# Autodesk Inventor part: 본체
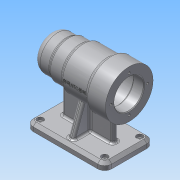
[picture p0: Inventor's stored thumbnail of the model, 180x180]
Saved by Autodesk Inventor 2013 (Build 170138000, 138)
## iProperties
Created: 2016-06
Part Number: 본체
Material: 알루미늄 6061
Document SubType Name: Modeling
Designer: Administrator
Density: 2.71 g/cm^3
Mass: 693.6 g
Surface Area: 666.256 cm^2
Volume: 255.941 cm^3
Author: Administrator
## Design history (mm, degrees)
sketch "스케치1"
  geometry: L1 (-46, 35)-(46, 35); L2 (56, 25)-(56, -25); L3 (46, -35)-(-46, -35); L4 (-56, -25)-(-56, 25); A1 r 10 centre (-46, 25) between (-46, 35) and (-56, 25); A2 r 10 centre (-46, -25) between (-56, -25) and (-46, -35); A3 r 10 centre (46, -25) between (46, -35) and (56, -25); A4 r 10 centre (46, 25) between (56, 25) and (46, 35); 3 further points
  constraints: 8 end point, 8 point on circle, 8 tangent, 4 centre point, 3 equal radius, 2 midpoint, 2 parallel, 1 horizontal, 1 horizontal alignment, 1 perpendicular, 1 vertical alignment
  dimensions: "d0" = 112 distance between parallel lines of L2 L4; "d2" = 70 distance between parallel lines of L1 L3; "d3" = 10 radius of A1
extrude "돌출1" new body sketch "스케치1" distance "d4" = 10; taper "d5" = 0 deg
sketch "스케치2"
  geometry: L1 (-56, 0)-(-56, 10) reference; L2 (-46, 10)-(-56, 10) reference; L3 (46, 10)-(-46, 10) reference; L4 (56, 10)-(46, 10) reference; L5 (56, 0)-(56, 10) reference; L6 (56, 0)-(46, 0) reference; L7 (46, 0)-(-46, 0) reference; L8 (-46, 0)-(-56, 0) reference; L9 (-56, 80)-(56, 80); L10 (56, 80)-(56, 114); L11 (56, 114)-(28, 114); L12 (28, 114)-(28, 110); L13 (28, 110)-(-11, 110); L14 (-11, 110)-(-11, 107); L15 (-11, 107)-(-31, 107); L16 (-31, 107)-(-31, 105); L17 (-31, 105)-(-46, 105); L18 (-56, 95)-(-56, 80); A1 r 10 centre (-46, 95) between (-46, 105) and (-56, 95); 1 further point
  constraints: 20 end point, 8 parallel, 2 perpendicular, 2 point on circle, 2 tangent, 1 centre point, 1 vertical alignment
  dimensions: "d6" = 112 distance of L9.start L9.end; "d8" = 70 distance between parallel lines of L3 L9; "d9" = 25 distance between parallel lines of L18 L16; "d10" = 45 distance between parallel lines of L14 L18; "d11" = 84 distance between parallel lines of L12 L18; "d12" = 68 diameter of L11 L9; "d13" = 60 diameter of L13 L9; "d14" = 54 diameter of L15 L9; "d15" = 50 diameter of L17 L9; "d16" = 10 radius of A1
revolve "회전1" sketch "스케치2" stored, may be unused: angle "d17" = 90 deg
sketch "스케치3"
  geometry: L1 (-56, 65)-(-56, 95) reference; L2 (-46, 55)-(-31, 55) reference; L3 (-31, 53)-(-11, 53) reference; L4 (-11, 50)-(28, 50) reference; L5 (28, 46)-(56, 46) reference; L6 (46, 10)-(-46, 10) reference; L7 (-46, 10)-(-56, 10) reference; L8 (56, 10)-(46, 10) reference; L9 (-36, 10)-(-36, 65); L10 (-36, 65)-(36, 65); L11 (36, 65)-(36, 10); L12 (56, 46)-(56, 114) reference; L13 (56, 0)-(56, 10) reference; L14 (-56, 0)-(-56, 10) reference; A1 r 10 centre (-46, 95) between (-46, 105) and (-56, 95) reference; A2 r 10 centre (-46, 65) between (-56, 65) and (-46, 55) reference; 2 further points
  constraints: 6 end point, 3 perpendicular, 2 point on line, 1 midpoint, 1 vertical alignment
  dimensions: "d18" = 20 distance between parallel lines of L11 L13; "d19" = 55 distance between parallel lines of L6 L10
extrude "돌출2" join sketch "스케치3" stored distance "d20" = 8; taper "d21" = 0 deg
sketch "스케치4"
  geometry: L1 (25, 10)-(-25, 10) reference; L2 (-35, 0)-(-35, 10) reference; L3 (-25, 10)-(-35, 10) reference; L4 (35, 10)-(25, 10) reference; L5 (35, 0)-(35, 10) reference; L6 (35, 0)-(25, 0) reference; L7 (25, 0)-(-25, 0) reference; L8 (-25, 0)-(-35, 0) reference; L9 (-4, 46.236)-(-4, 10) reference; L10 (4, 10)-(4, 46.236) reference; L11 (-8.043, 64.83)-(8.043, 64.83); L12 (8.043, 64.83)-(28, 10); L13 (-8.043, 64.83)-(-28, 10); A1 r 34 centre (0, 80) between (4, 46.236) and (-4, 46.236) reference; 1 further point
  constraints: 6 end point, 2 point on line, 1 equal length, 1 perpendicular
  dimensions: "d23" = 7 distance from line of L12.end L5; "d24" = 7 distance from line of L13.end L2; "d25" = 110 deg angle of L13 L3; "d26" = 54.83005 distance between parallel lines of L1 L11
extrude "돌출3" join sketch "스케치4" stored distance "d28" = 8; taper "d29" = 0 deg
hole "구멍1" diameter "d32" = 42; stored, may be unused: countersink angle "d36" = 90 deg, drill point angle "d38" = 0 deg; dims "d30" = 10, "d31" = 10, "d33" = 6, "d34" = 4, "d35" = 2, "d37" = 15
hole "구멍2" diameter "d41" = 48; stored, may be unused: countersink angle "d45" = 90 deg, drill point angle "d47" = 0 deg; dims "d39" = 10, "d40" = 10, "d42" = 6, "d43" = 4, "d44" = 2, "d46" = 54
hole "구멍3" diameter "d50" = 42; stored, may be unused: countersink angle "d54" = 90 deg, drill point angle "d56" = 0 deg; dims "d48" = 10, "d49" = 10, "d51" = 6, "d52" = 4, "d53" = 2, "d55" = 12
hole "구멍4" diameter "d59" = 35; stored, may be unused: countersink angle "d63" = 90 deg, drill point angle "d65" = 0 deg; dims "d57" = 10, "d58" = 10, "d60" = 6, "d61" = 4, "d62" = 2, "d64" = 18
hole "구멍5" diameter "d68" = 32; stored, may be unused: countersink angle "d72" = 90 deg, drill point angle "d74" = 0 deg; dims "d66" = 10, "d67" = 10, "d69" = 6, "d70" = 4, "d71" = 2, "d73" = 4
hole "구멍6" diameter "d77" = 21; stored, may be unused: countersink angle "d81" = 90 deg, drill point angle "d83" = 0 deg; dims "d75" = 10, "d76" = 10, "d78" = 6, "d79" = 4, "d80" = 2, "d82" = 3
sketch "스케치5"
  geometry: A1 r 34 centre (0, 0) between (-33.764, -4) and (-33.764, 4) reference; 2 further points
  constraints: 1 horizontal alignment
  dimensions: "d84" = 26 distance of point (-26, 0) A1.centre
hole "구멍7" sketch "스케치5" at (-26, 0) diameter "d85" = 3.242; stored, may be unused: countersink angle "d89" = 90 deg, drill point angle "d91" = 118 deg; dims "d86" = 8, "d87" = 4, "d88" = 2, "d90" = 11
sketch "스케치6"
  geometry: L1 (-56, 25)-(-56, -25) reference; L2 (46, 35)-(-46, 35) reference; L3 (56, -25)-(56, 25) reference; L4 (-46, -35)-(46, -35) reference; C1 r 4.5 at (-46, 25); C2 r 4.5 at (46, 25); C3 r 4.5 at (46, -25); C4 r 4.5 at (-46, -25); A1 r 10 centre (-46, 25) between (-46, 35) and (-56, 25) reference; A2 r 10 centre (46, 25) between (56, 25) and (46, 35) reference; A3 r 10 centre (46, -25) between (46, -35) and (56, -25) reference; A4 r 10 centre (-46, -25) between (-56, -25) and (-46, -35) reference; 1 further point
  constraints: 4 centre point, 3 equal radius, 2 horizontal alignment, 2 vertical alignment
  dimensions: "d95" = 92 distance of C3.centre C4.centre; "d97" = 50 distance of C4.centre C1.centre; "d98" = 25 vertical distance of C1.centre point (0, 0); "d99" = 46 horizontal distance of point (0, 0) C2.centre; "d100" = 9 diameter of C1
hole "구멍8" sketch "스케치6" at (46, -25), (-46, 25), (46, 25), (-46, -25) diameter "d101" = 5; stored, may be unused: countersink angle "d105" = 90 deg, drill point angle "d107" = 0 deg; dims "d102" = 8, "d103" = 9, "d104" = 4, "d106" = 11
chamfer "모따기1" distance "d108" = 4; stored, may be unused: second distance "d109" = 2, angle "d110" = 45 deg
chamfer "모따기2" distance "d111" = 1; stored, may be unused: second distance "d112" = 2, angle "d113" = 45 deg
fillet "모깎기1" dims "d114" = 0.3
fillet "모깎기2" dims "d115" = 3
fillet "모깎기3" dims "d116" = 3
fillet "모깎기4" dims "d117" = 3
fillet "모깎기5" dims "d118" = 3
fillet "모깎기6" dims "d119" = 3
node "작업 평면1"
sketch "스케치7"
  geometry: L1 (56, 46)-(56, 114) reference; 3 further points
  constraints: 1 horizontal alignment, 1 midpoint, 1 other
  dimensions: "d121" = 48 distance from line of point (8, 80) L1
feature "엠보싱1" sketch "스케치7" dims "d0" = 112, "d122" = 0.5, "d123" = 0
node "솔리드1"
pattern_circular "원형 패턴1" dims angle "d93" = 360 deg
node "투영된 루프1"
other parameters: "d27" = 8
